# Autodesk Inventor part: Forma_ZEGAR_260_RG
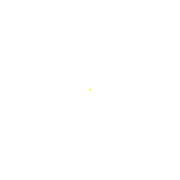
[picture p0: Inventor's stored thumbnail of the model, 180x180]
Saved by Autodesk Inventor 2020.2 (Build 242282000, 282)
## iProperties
Created: 2015-01
Part Number: Forma_ZEGAR_260_RG
Material: Ogólny
Document SubType Name: Modeling
Designer: F.Stasiak
Density: 1 g/cm^3
Appearance: Domyślna
Catalog Web Link: www.expertbooks.pl
Manager: www.cadconsulting.pl
Company: Fabian Stasiak CAD Consulting
Author: F.Stasiak
Subject: Zbiór ćwiczeń. Autodesk Inventor 2020. Kurs Professional
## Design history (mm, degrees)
node "Położenie przewężki 1_PZ:1"
node "Bryła1"
